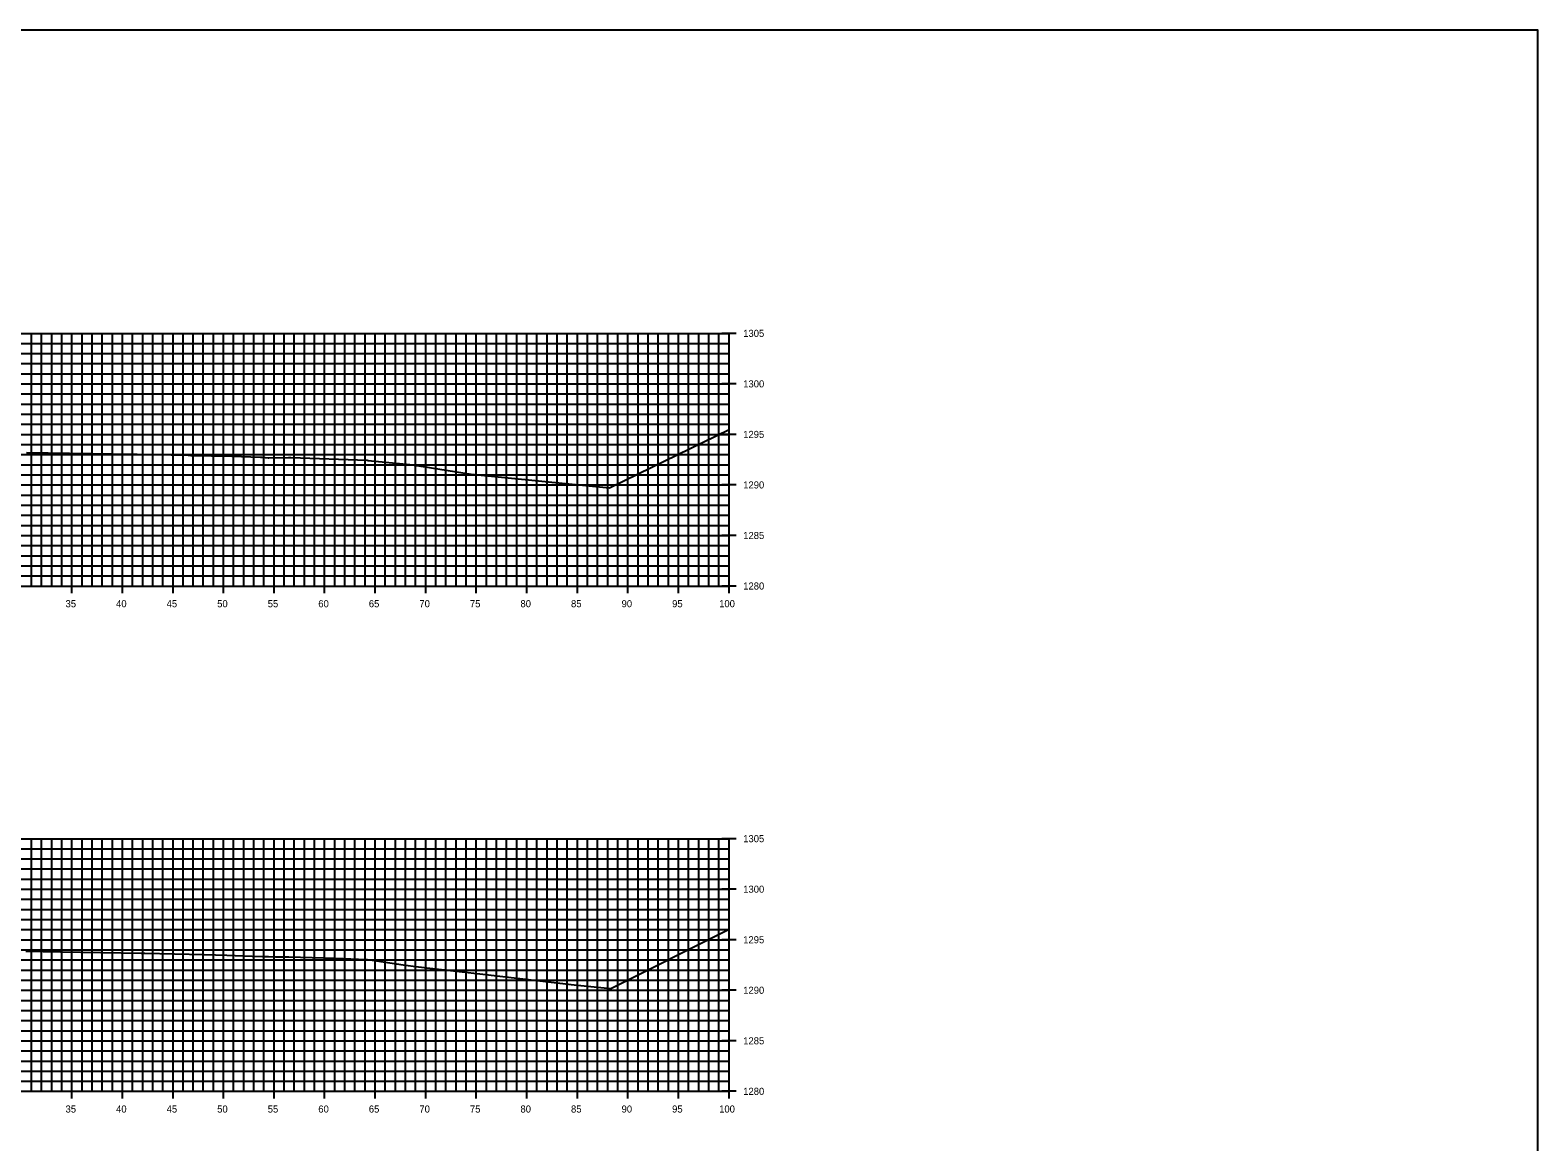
# Model space of a CAD drawing. Extents: x 674939 to 678919, y 750652 to 765176.
# Drawn here: x 678769.4 to 678918.5, y 754942.6 to 755052.6 of the extents above; entities that cross this region are included whole.
import ezdxf

# ---------------------------------------------------------------- set-up
doc = ezdxf.new("R2010")
doc.units = 0
for name, color, linetype in [('R_Axis', 7, 'Continuous'), ('R_Axis Annot', 7, 'Continuous'), ('R_Exist Surface', 7, 'Continuous'), ('R_Grid', 7, 'Continuous'), ('R_No Plot', 7, 'Continuous')]:
    doc.layers.add(name, color=color, linetype=linetype)

msp = doc.modelspace()

# ---------------------------------------------------------------- linework, layer by layer
at = {"layer": 'R_Axis'}
for p, q in [((678839.23, 755022.55), (678837.83, 755022.55)), ((678838.53, 754997.55), (678838.53, 755022.55)), ((678839.23, 755017.55), (678837.83, 755017.55)), ((678839.23, 755012.55), (678837.83, 755012.55)), ((678839.23, 755007.55), (678837.83, 755007.55)), ((678839.23, 755002.55), (678837.83, 755002.55)), ((678773.53, 754996.85), (678773.53, 754998.25)), ((678778.53, 754996.85), (678778.53, 754998.25)), ((678783.53, 754996.85), (678783.53, 754998.25)), ((678788.53, 754996.85), (678788.53, 754998.25)), ((678793.53, 754996.85), (678793.53, 754998.25)), ((678798.53, 754996.85), (678798.53, 754998.25)), ((678803.53, 754996.85), (678803.53, 754998.25)), ((678808.53, 754996.85), (678808.53, 754998.25)), ((678813.53, 754996.85), (678813.53, 754998.25)), ((678818.53, 754996.85), (678818.53, 754998.25)), ((678823.53, 754996.85), (678823.53, 754998.25)), ((678828.53, 754996.85), (678828.53, 754998.25)), ((678833.53, 754996.85), (678833.53, 754998.25)), ((678838.53, 754996.85), (678838.53, 754998.25)), ((678638.53, 754997.55), (678838.53, 754997.55)), ((678839.23, 754997.55), (678837.83, 754997.55)), ((678839.23, 754972.55), (678837.83, 754972.55)), ((678838.53, 754947.55), (678838.53, 754972.55)), ((678839.23, 754967.55), (678837.83, 754967.55)), ((678839.23, 754962.55), (678837.83, 754962.55)), ((678839.23, 754957.55), (678837.83, 754957.55)), ((678839.23, 754952.55), (678837.83, 754952.55)), ((678638.53, 754947.55), (678838.53, 754947.55)), ((678773.53, 754946.85), (678773.53, 754948.25)), ((678778.53, 754946.85), (678778.53, 754948.25)), ((678783.53, 754946.85), (678783.53, 754948.25)), ((678788.53, 754946.85), (678788.53, 754948.25)), ((678793.53, 754946.85), (678793.53, 754948.25)), ((678798.53, 754946.85), (678798.53, 754948.25)), ((678803.53, 754946.85), (678803.53, 754948.25)), ((678808.53, 754946.85), (678808.53, 754948.25)), ((678813.53, 754946.85), (678813.53, 754948.25)), ((678818.53, 754946.85), (678818.53, 754948.25)), ((678823.53, 754946.85), (678823.53, 754948.25)), ((678828.53, 754946.85), (678828.53, 754948.25)), ((678833.53, 754946.85), (678833.53, 754948.25)), ((678839.23, 754947.55), (678837.83, 754947.55)), ((678838.53, 754946.85), (678838.53, 754948.25))]:
    msp.add_line(p, q, dxfattribs=at)
at = {"layer": 'R_Exist Surface'}
for points in [[(678769.04, 755010.77), (678779.68, 755010.6), (678779.96, 755010.6), (678779.99, 755010.6), (678785.02, 755010.48), (678785.3, 755010.47), (678789.36, 755010.39), (678792.2, 755010.3), (678792.28, 755010.3), (678792.28, 755010.3), (678792.35, 755010.3), (678792.93, 755010.24), (678792.95, 755010.24), (678793.01, 755010.24), (678794.94, 755010.26), (678795.19, 755010.25), (678802.73, 755010), (678802.75, 755010), (678802.84, 755009.98), (678806.94, 755009.56), (678807.62, 755009.48), (678808.26, 755009.38), (678813.03, 755008.61), (678820.01, 755007.93), (678826.71, 755007.27), (678829.53, 755008.65), (678838.53, 755013.05)], [(678768.98, 754961.41), (678772.41, 754961.36), (678780.38, 754961.22), (678780.74, 754961.21), (678786.62, 754961.08), (678788.84, 754961.03), (678791.36, 754960.94), (678792.38, 754960.9), (678792.44, 754960.9), (678792.72, 754960.89), (678792.96, 754960.88), (678793.66, 754960.87), (678794.15, 754960.87), (678794.98, 754960.87), (678799.6, 754960.72), (678801.88, 754960.63), (678802.72, 754960.59), (678802.84, 754960.57), (678802.99, 754960.55), (678806.29, 754960.07), (678807.29, 754959.94), (678808.63, 754959.77), (678813.87, 754959.16), (678823.22, 754958.1), (678826.85, 754957.72), (678838.53, 754963.61)]]:
    msp.add_lwpolyline(points, dxfattribs=at)
at = {"layer": 'R_Grid'}
for p, q in [((678638.53, 755022.55), (678838.53, 755022.55)), ((678769.53, 754997.55), (678769.53, 755022.55)), ((678770.53, 754997.55), (678770.53, 755022.55)), ((678771.53, 754997.55), (678771.53, 755022.55)), ((678772.53, 754997.55), (678772.53, 755022.55)), ((678773.53, 754997.55), (678773.53, 755022.55)), ((678774.53, 754997.55), (678774.53, 755022.55)), ((678775.53, 754997.55), (678775.53, 755022.55)), ((678776.53, 754997.55), (678776.53, 755022.55)), ((678777.53, 754997.55), (678777.53, 755022.55)), ((678778.53, 754997.55), (678778.53, 755022.55)), ((678779.53, 754997.55), (678779.53, 755022.55)), ((678780.53, 754997.55), (678780.53, 755022.55)), ((678781.53, 754997.55), (678781.53, 755022.55)), ((678782.53, 754997.55), (678782.53, 755022.55)), ((678783.53, 754997.55), (678783.53, 755022.55)), ((678784.53, 754997.55), (678784.53, 755022.55)), ((678785.53, 754997.55), (678785.53, 755022.55)), ((678786.53, 754997.55), (678786.53, 755022.55)), ((678787.53, 754997.55), (678787.53, 755022.55)), ((678788.53, 754997.55), (678788.53, 755022.55)), ((678789.53, 754997.55), (678789.53, 755022.55)), ((678790.53, 754997.55), (678790.53, 755022.55)), ((678791.53, 754997.55), (678791.53, 755022.55)), ((678792.53, 754997.55), (678792.53, 755022.55)), ((678793.53, 754997.55), (678793.53, 755022.55)), ((678794.53, 754997.55), (678794.53, 755022.55)), ((678795.53, 754997.55), (678795.53, 755022.55)), ((678796.53, 754997.55), (678796.53, 755022.55)), ((678797.53, 754997.55), (678797.53, 755022.55)), ((678798.53, 754997.55), (678798.53, 755022.55)), ((678799.53, 754997.55), (678799.53, 755022.55)), ((678800.53, 754997.55), (678800.53, 755022.55)), ((678801.53, 754997.55), (678801.53, 755022.55)), ((678802.53, 754997.55), (678802.53, 755022.55)), ((678803.53, 754997.55), (678803.53, 755022.55)), ((678804.53, 754997.55), (678804.53, 755022.55)), ((678805.53, 754997.55), (678805.53, 755022.55)), ((678806.53, 754997.55), (678806.53, 755022.55)), ((678807.53, 754997.55), (678807.53, 755022.55)), ((678808.53, 754997.55), (678808.53, 755022.55)), ((678809.53, 754997.55), (678809.53, 755022.55)), ((678810.53, 754997.55), (678810.53, 755022.55)), ((678811.53, 754997.55), (678811.53, 755022.55)), ((678812.53, 754997.55), (678812.53, 755022.55)), ((678813.53, 754997.55), (678813.53, 755022.55)), ((678814.53, 754997.55), (678814.53, 755022.55)), ((678815.53, 754997.55), (678815.53, 755022.55)), ((678816.53, 754997.55), (678816.53, 755022.55)), ((678817.53, 754997.55), (678817.53, 755022.55)), ((678818.53, 754997.55), (678818.53, 755022.55)), ((678819.53, 754997.55), (678819.53, 755022.55)), ((678820.53, 754997.55), (678820.53, 755022.55)), ((678821.53, 754997.55), (678821.53, 755022.55)), ((678822.53, 754997.55), (678822.53, 755022.55)), ((678823.53, 754997.55), (678823.53, 755022.55)), ((678824.53, 754997.55), (678824.53, 755022.55)), ((678825.53, 754997.55), (678825.53, 755022.55)), ((678826.53, 754997.55), (678826.53, 755022.55)), ((678827.53, 754997.55), (678827.53, 755022.55)), ((678828.53, 754997.55), (678828.53, 755022.55)), ((678829.53, 754997.55), (678829.53, 755022.55)), ((678830.53, 754997.55), (678830.53, 755022.55)), ((678831.53, 754997.55), (678831.53, 755022.55)), ((678832.53, 754997.55), (678832.53, 755022.55)), ((678833.53, 754997.55), (678833.53, 755022.55)), ((678834.53, 754997.55), (678834.53, 755022.55)), ((678835.53, 754997.55), (678835.53, 755022.55)), ((678836.53, 754997.55), (678836.53, 755022.55)), ((678837.53, 754997.55), (678837.53, 755022.55)), ((678838.53, 754997.55), (678838.53, 755022.55)), ((678638.53, 755021.55), (678838.53, 755021.55)), ((678638.53, 755020.55), (678838.53, 755020.55)), ((678638.53, 755019.55), (678838.53, 755019.55)), ((678638.53, 755018.55), (678838.53, 755018.55)), ((678638.53, 755017.55), (678838.53, 755017.55)), ((678638.53, 755016.55), (678838.53, 755016.55)), ((678638.53, 755015.55), (678838.53, 755015.55)), ((678638.53, 755014.55), (678838.53, 755014.55)), ((678638.53, 755013.55), (678838.53, 755013.55)), ((678638.53, 755012.55), (678838.53, 755012.55)), ((678638.53, 755011.55), (678838.53, 755011.55)), ((678638.53, 755010.55), (678838.53, 755010.55)), ((678638.53, 755009.55), (678838.53, 755009.55)), ((678638.53, 755008.55), (678838.53, 755008.55)), ((678638.53, 755007.55), (678838.53, 755007.55)), ((678638.53, 755006.55), (678838.53, 755006.55)), ((678638.53, 755005.55), (678838.53, 755005.55)), ((678638.53, 755004.55), (678838.53, 755004.55)), ((678638.53, 755003.55), (678838.53, 755003.55)), ((678638.53, 755002.55), (678838.53, 755002.55)), ((678638.53, 755001.55), (678838.53, 755001.55)), ((678638.53, 755000.55), (678838.53, 755000.55)), ((678638.53, 754999.55), (678838.53, 754999.55)), ((678638.53, 754998.55), (678838.53, 754998.55)), ((678638.53, 754997.55), (678838.53, 754997.55)), ((678638.53, 754972.55), (678838.53, 754972.55)), ((678769.53, 754947.55), (678769.53, 754972.55)), ((678770.53, 754947.55), (678770.53, 754972.55)), ((678771.53, 754947.55), (678771.53, 754972.55)), ((678772.53, 754947.55), (678772.53, 754972.55)), ((678773.53, 754947.55), (678773.53, 754972.55)), ((678774.53, 754947.55), (678774.53, 754972.55)), ((678775.53, 754947.55), (678775.53, 754972.55)), ((678776.53, 754947.55), (678776.53, 754972.55)), ((678777.53, 754947.55), (678777.53, 754972.55)), ((678778.53, 754947.55), (678778.53, 754972.55)), ((678779.53, 754947.55), (678779.53, 754972.55)), ((678780.53, 754947.55), (678780.53, 754972.55)), ((678781.53, 754947.55), (678781.53, 754972.55)), ((678782.53, 754947.55), (678782.53, 754972.55)), ((678783.53, 754947.55), (678783.53, 754972.55)), ((678784.53, 754947.55), (678784.53, 754972.55)), ((678785.53, 754947.55), (678785.53, 754972.55)), ((678786.53, 754947.55), (678786.53, 754972.55)), ((678787.53, 754947.55), (678787.53, 754972.55)), ((678788.53, 754947.55), (678788.53, 754972.55)), ((678789.53, 754947.55), (678789.53, 754972.55)), ((678790.53, 754947.55), (678790.53, 754972.55)), ((678791.53, 754947.55), (678791.53, 754972.55)), ((678792.53, 754947.55), (678792.53, 754972.55)), ((678793.53, 754947.55), (678793.53, 754972.55)), ((678794.53, 754947.55), (678794.53, 754972.55)), ((678795.53, 754947.55), (678795.53, 754972.55)), ((678796.53, 754947.55), (678796.53, 754972.55)), ((678797.53, 754947.55), (678797.53, 754972.55)), ((678798.53, 754947.55), (678798.53, 754972.55)), ((678799.53, 754947.55), (678799.53, 754972.55)), ((678800.53, 754947.55), (678800.53, 754972.55)), ((678801.53, 754947.55), (678801.53, 754972.55)), ((678802.53, 754947.55), (678802.53, 754972.55)), ((678803.53, 754947.55), (678803.53, 754972.55)), ((678804.53, 754947.55), (678804.53, 754972.55)), ((678805.53, 754947.55), (678805.53, 754972.55)), ((678806.53, 754947.55), (678806.53, 754972.55)), ((678807.53, 754947.55), (678807.53, 754972.55)), ((678808.53, 754947.55), (678808.53, 754972.55)), ((678809.53, 754947.55), (678809.53, 754972.55)), ((678810.53, 754947.55), (678810.53, 754972.55)), ((678811.53, 754947.55), (678811.53, 754972.55)), ((678812.53, 754947.55), (678812.53, 754972.55)), ((678813.53, 754947.55), (678813.53, 754972.55)), ((678814.53, 754947.55), (678814.53, 754972.55)), ((678815.53, 754947.55), (678815.53, 754972.55)), ((678816.53, 754947.55), (678816.53, 754972.55)), ((678817.53, 754947.55), (678817.53, 754972.55)), ((678818.53, 754947.55), (678818.53, 754972.55)), ((678819.53, 754947.55), (678819.53, 754972.55)), ((678820.53, 754947.55), (678820.53, 754972.55)), ((678821.53, 754947.55), (678821.53, 754972.55)), ((678822.53, 754947.55), (678822.53, 754972.55)), ((678823.53, 754947.55), (678823.53, 754972.55)), ((678824.53, 754947.55), (678824.53, 754972.55)), ((678825.53, 754947.55), (678825.53, 754972.55)), ((678826.53, 754947.55), (678826.53, 754972.55)), ((678827.53, 754947.55), (678827.53, 754972.55)), ((678828.53, 754947.55), (678828.53, 754972.55)), ((678829.53, 754947.55), (678829.53, 754972.55)), ((678830.53, 754947.55), (678830.53, 754972.55)), ((678831.53, 754947.55), (678831.53, 754972.55)), ((678832.53, 754947.55), (678832.53, 754972.55)), ((678833.53, 754947.55), (678833.53, 754972.55)), ((678834.53, 754947.55), (678834.53, 754972.55)), ((678835.53, 754947.55), (678835.53, 754972.55)), ((678836.53, 754947.55), (678836.53, 754972.55)), ((678837.53, 754947.55), (678837.53, 754972.55)), ((678838.53, 754947.55), (678838.53, 754972.55)), ((678638.53, 754971.55), (678838.53, 754971.55)), ((678638.53, 754970.55), (678838.53, 754970.55)), ((678638.53, 754969.55), (678838.53, 754969.55)), ((678638.53, 754968.55), (678838.53, 754968.55)), ((678638.53, 754967.55), (678838.53, 754967.55)), ((678638.53, 754966.55), (678838.53, 754966.55)), ((678638.53, 754965.55), (678838.53, 754965.55)), ((678638.53, 754964.55), (678838.53, 754964.55)), ((678638.53, 754963.55), (678838.53, 754963.55)), ((678638.53, 754962.55), (678838.53, 754962.55)), ((678638.53, 754961.55), (678838.53, 754961.55)), ((678638.53, 754960.55), (678838.53, 754960.55)), ((678638.53, 754959.55), (678838.53, 754959.55)), ((678638.53, 754958.55), (678838.53, 754958.55)), ((678638.53, 754957.55), (678838.53, 754957.55)), ((678638.53, 754956.55), (678838.53, 754956.55)), ((678638.53, 754955.55), (678838.53, 754955.55)), ((678638.53, 754954.55), (678838.53, 754954.55)), ((678638.53, 754953.55), (678838.53, 754953.55)), ((678638.53, 754952.55), (678838.53, 754952.55)), ((678638.53, 754951.55), (678838.53, 754951.55)), ((678638.53, 754950.55), (678838.53, 754950.55)), ((678638.53, 754949.55), (678838.53, 754949.55)), ((678638.53, 754948.55), (678838.53, 754948.55)), ((678638.53, 754947.55), (678838.53, 754947.55))]:
    msp.add_line(p, q, dxfattribs=at)
at = {"layer": 'R_No Plot'}
msp.add_lwpolyline([(678578.53, 754832.55), (678918.53, 754832.55), (678918.53, 755052.55), (678578.53, 755052.55)], close=True, dxfattribs=at)

# ---------------------------------------------------------------- texts
at = {"layer": 'R_Axis Annot'}
for s, p in [('1305', (678839.93, 755022.2)), ('1300', (678839.93, 755017.2)), ('1295', (678839.93, 755012.2)), ('1290', (678839.93, 755007.2)), ('1285', (678839.93, 755002.2)), ('1280', (678839.93, 754997.2)), ('35', (678772.9, 754995.45)), ('40', (678777.9, 754995.45)), ('45', (678782.9, 754995.45)), ('50', (678787.9, 754995.45)), ('55', (678792.9, 754995.45)), ('60', (678797.9, 754995.45)), ('65', (678802.9, 754995.45)), ('70', (678807.9, 754995.45)), ('75', (678812.9, 754995.45)), ('80', (678817.9, 754995.45)), ('85', (678822.9, 754995.45)), ('90', (678827.9, 754995.45)), ('95', (678832.9, 754995.45)), ('100', (678837.55, 754995.45)), ('1305', (678839.93, 754972.2)), ('1300', (678839.93, 754967.2)), ('1295', (678839.93, 754962.2)), ('1290', (678839.93, 754957.2)), ('1285', (678839.93, 754952.2)), ('1280', (678839.93, 754947.2)), ('35', (678772.9, 754945.45)), ('40', (678777.9, 754945.45)), ('45', (678782.9, 754945.45)), ('50', (678787.9, 754945.45)), ('55', (678792.9, 754945.45)), ('60', (678797.9, 754945.45)), ('65', (678802.9, 754945.45)), ('70', (678807.9, 754945.45)), ('75', (678812.9, 754945.45)), ('80', (678817.9, 754945.45)), ('85', (678822.9, 754945.45)), ('90', (678827.9, 754945.45)), ('95', (678832.9, 754945.45)), ('100', (678837.55, 754945.45))]:
    msp.add_text(s, height=0.7, dxfattribs=at).set_placement(p)

doc.saveas('drawing.dxf')
